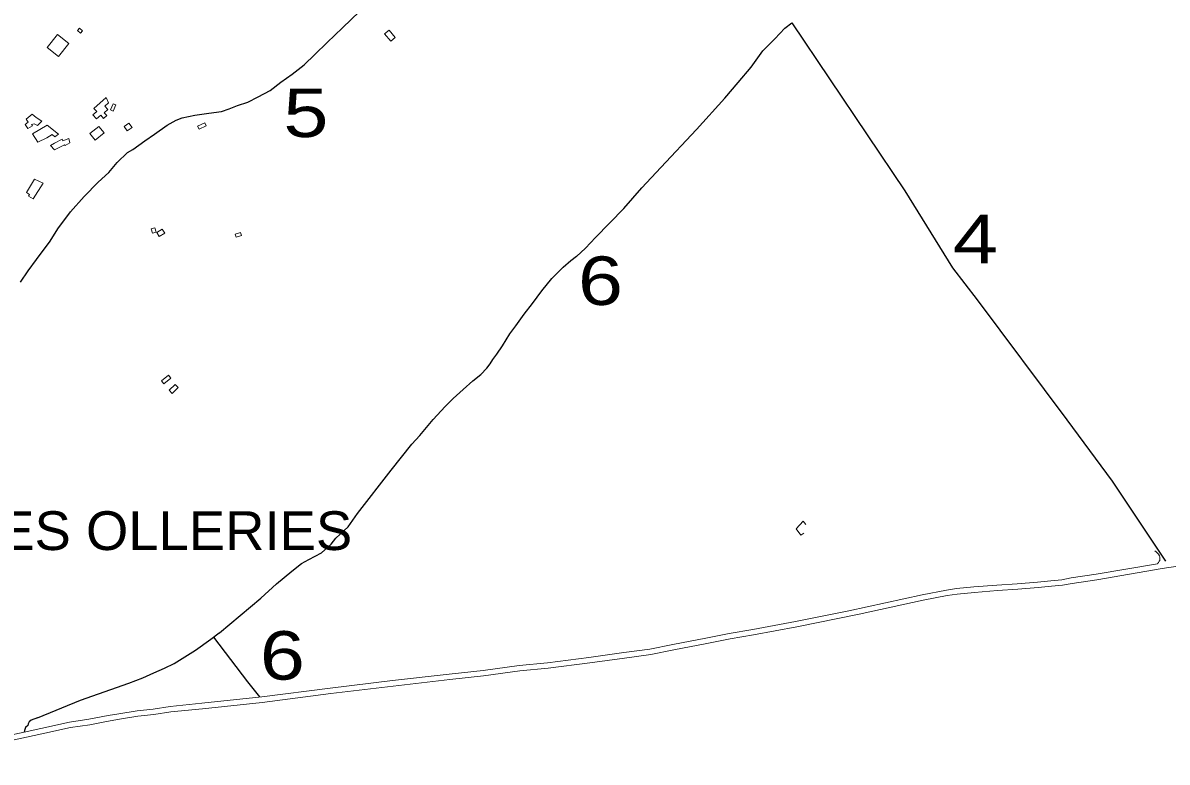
# Model space of a CAD drawing. Extents: x 476989 to 498418, y 4381813 to 4416555.
# Drawn here: x 485600 to 486780, y 4384896 to 4385659 of the extents above; entities that cross this region are included whole.
import ezdxf
from ezdxf.enums import TextEntityAlignment as Align

# ---------------------------------------------------------------- set-up
doc = ezdxf.new("R2010")
doc.units = 0
doc.header["$LTSCALE"] = 20
doc.linetypes.add('MEDIUM_DASHED', pattern=[4.5, 3, -1.5])
for name, color, linetype, lineweight in [('13', 7, 'Continuous', 13), ('36', 7, 'Continuous', 13), ('47', 7, 'Continuous', 13), ('48', 7, 'MEDIUM_DASHED', 13), ('6', 7, 'Continuous', 25)]:
    doc.layers.add(name, color=color, linetype=linetype, lineweight=lineweight)
doc.layers.add('7', color=7, linetype='Continuous')

msp = doc.modelspace()

# ---------------------------------------------------------------- linework, layer by layer
at = {"layer": '36'}
for points in [[(485587.94, 4384918.87), (485619.65, 4384925.47), (485648.99, 4384932.03), (485669.04, 4384935.03), (485686.15, 4384938.36), (485699.65, 4384940.84), (485718.69, 4384943.79), (485734.94, 4384945.58), (485752.53, 4384948.26), (485785.29, 4384951.54), (485846.98, 4384958.08), (485917.59, 4384967.28), (485981.92, 4384974.91), (486040.54, 4384981.65), (486075.35, 4384985.5), (486112.55, 4384990.45), (486141.85, 4384993.18), (486184.72, 4384998.94), (486220.81, 4385003.83), (486247.67, 4385007.48), (486271.61, 4385012.25), (486305.54, 4385018.75), (486329.76, 4385023.58), (486353.89, 4385027.57), (486398.31, 4385035.88), (486461.13, 4385048.69), (486462.73, 4385049.14), (486528.81, 4385063.65), (486553.7, 4385068.46), (486563.83, 4385069.82), (486581.63, 4385071.52), (486605.36, 4385073.58), (486626.31, 4385074.93), (486647.28, 4385076.51), (486661.18, 4385077.81), (486672.55, 4385078.92), (486682.57, 4385080.87), (486708.05, 4385084.63), (486775.37, 4385096.2), (486800.8, 4385100.04)], [(485601.44, 4384927.38), (485618.46, 4384930.95), (485647.97, 4384937.54), (485668, 4384940.55), (485688.12, 4384944.59), (485698.86, 4384946.38), (485717.96, 4384949.34), (485734.21, 4384951.14), (485751.82, 4384953.82), (485784.71, 4384957.11), (485846.33, 4384963.64), (485916.89, 4384972.84), (485981.27, 4384980.47), (486039.91, 4384987.22), (486074.67, 4384991.06), (486111.92, 4384996.02), (486141.22, 4384998.75), (486183.97, 4385004.49), (486220.05, 4385009.38), (486246.73, 4385013.02), (486270.53, 4385017.75), (486304.46, 4385024.25), (486328.75, 4385029.09), (486352.92, 4385033.1), (486397.22, 4385041.38), (486452.17, 4385052.61), (486452.19, 4385052.58), (486527.68, 4385069.14), (486552.8, 4385074), (486563.2, 4385075.39), (486581.12, 4385077.1), (486604.95, 4385079.16), (486625.92, 4385080.52), (486646.81, 4385082.09), (486660.65, 4385083.38), (486671.74, 4385084.47), (486681.62, 4385086.4), (486707.17, 4385090.17), (486770.61, 4385101.07)], [(485422.69, 4384896.4), (485445.04, 4384898.28), (485457.06, 4384899.22), (485464.89, 4384900.34), (485474.69, 4384902.21), (485508.34, 4384907.79), (485538.44, 4384915.04), (485558.81, 4384919.82), (485586.93, 4384924.38), (485601.44, 4384927.38)]]:
    msp.add_lwpolyline(points, dxfattribs=at)
msp.add_spline([(486767.68, 4385114.39), (486772.5, 4385109.36), (486772.99, 4385106.58), (486772.97, 4385105.38), (486772.81, 4385104.41), (486772.42, 4385103.66), (486770.74, 4385101.28), (486770.61, 4385101.07)], degree=3, dxfattribs=at)
at = {"layer": '47'}
for points in [[(485658.29, 4385653.66), (485661.38, 4385650.92), (485659.34, 4385648.62), (485656.25, 4385651.36)], [(485635.68, 4385647.23), (485647.33, 4385637.86), (485636.56, 4385624.48), (485624.91, 4385633.85)], [(485973.2, 4385647.8), (485979.51, 4385640.27), (485984.18, 4385644.19), (485977.87, 4385651.72)], [(485686, 4385582.05), (485673.31, 4385570.9), (485676.11, 4385567.69), (485672.26, 4385564.34), (485675.87, 4385560.17), (485680.34, 4385564.05), (485683.31, 4385560.61), (485686.6, 4385563.46), (485683.93, 4385566.52), (485687.71, 4385569.83), (485684.68, 4385573.28), (485688.41, 4385576.56)], [(485693.04, 4385575.65), (485690.28, 4385569.34), (485693, 4385568.15), (485695.76, 4385574.46)], [(485619.69, 4385557.64), (485613.67, 4385561.55), (485609.59, 4385565.06), (485603.44, 4385559.82), (485605.27, 4385556.65), (485602.46, 4385554.21), (485604.95, 4385550.05), (485609.94, 4385552.83), (485608.92, 4385554.42), (485611.48, 4385555.06), (485615.13, 4385553.2)], [(485625.19, 4385553.51), (485610.05, 4385544.72), (485615.41, 4385536.24), (485624.62, 4385540.46), (485630.23, 4385543.98), (485632.89, 4385541.54), (485636.84, 4385544.49)], [(485683.68, 4385545.62), (485674.4, 4385538.3), (485669.11, 4385545), (485678.39, 4385552.32)], [(485709.41, 4385555.83), (485704.45, 4385552.39), (485707.72, 4385547.67), (485712.68, 4385551.11)], [(485787.53, 4385556.14), (485780.27, 4385552.57), (485781.8, 4385549.46), (485789.06, 4385553.03)], [(485647.5, 4385539.76), (485641.24, 4385537.45), (485640.36, 4385539.11), (485632.5, 4385534.95), (485628.57, 4385532.83), (485632.55, 4385528.34), (485642.83, 4385533.52), (485643.57, 4385532.76), (485648.26, 4385535.32)], [(485620.73, 4385493.69), (485610.59, 4385477.56), (485605.81, 4385480.55), (485606.79, 4385482.13), (485603.55, 4385484.13), (485612.08, 4385497.96)], [(485736, 4385447.7), (485737.37, 4385443.37), (485733.82, 4385442.25), (485732.45, 4385446.58)], [(485743.71, 4385446.46), (485738.03, 4385443.02), (485740.6, 4385438.78), (485746.28, 4385442.22)], [(485819.05, 4385441.33), (485824.55, 4385443.01), (485825.55, 4385439.73), (485820.05, 4385438.05)], [(485750.18, 4385295.54), (485742.99, 4385289.76), (485745.4, 4385286.76), (485752.59, 4385292.54)], [(485756.95, 4385286.22), (485750.76, 4385280.13), (485753.96, 4385276.88), (485760.15, 4385282.97)]]:
    msp.add_lwpolyline(points, close=True, dxfattribs=at)
at = {"layer": '48'}
msp.add_lwpolyline([(486407.83, 4385141.71), (486405.11, 4385144.87), (486397.87, 4385137.02), (486402.73, 4385130.49), (486405.67, 4385132.69)], dxfattribs=at)
at = {"layer": '6'}
for points in [[(485597.52, 4385391.7), (485605.43, 4385403.19), (485614.06, 4385415.16), (485627.96, 4385433.84), (485636.16, 4385446.72), (485649.17, 4385464.38), (485663.28, 4385479.94), (485677.54, 4385494.69), (485688.56, 4385504.94), (485697.1, 4385515.25), (485707.8, 4385525.57), (485713.5, 4385528.66), (485725.91, 4385537.47), (485735.62, 4385544.46), (485748.75, 4385553.59), (485758, 4385558.72), (485764.17, 4385561.06), (485777.52, 4385563.88), (485791.81, 4385566), (485804.8, 4385567.91), (485812.68, 4385570.49), (485821.36, 4385573.88), (485831.97, 4385577.48), (485842.83, 4385582.78), (485855.2, 4385589.43), (485865.96, 4385597.89), (485877.72, 4385606.2), (485890.29, 4385615.9), (485901.17, 4385626.54), (485913.87, 4385638.89), (485929.7, 4385654.12), (485947.21, 4385671)], [(486171.07, 4385418.2), (486180.45, 4385426.71), (486190.85, 4385437.61), (486220.01, 4385467.74), (486238.45, 4385489.11), (486258.12, 4385510.06), (486294.91, 4385549.3), (486324.2, 4385581.38), (486338.08, 4385597.54), (486351.44, 4385613.56), (486363.48, 4385630.43), (486375.73, 4385642.67), (486386.01, 4385653.7), (486393.28, 4385659.16)], [(486779.18, 4385103.59), (486724.1, 4385186.32), (486677.34, 4385249.63), (486584.76, 4385373.47), (486559.43, 4385406.45), (486510.37, 4385486.01), (486393.48, 4385659.09)], [(485802.83, 4385029.77), (485845.6, 4385065.72), (485861.7, 4385080.31), (485877.49, 4385093.53), (485887.3, 4385101.32), (485895.1, 4385105.6), (485908.18, 4385112.39), (485917.95, 4385121.44), (485922.84, 4385127.37), (485927.25, 4385131.59), (485935.63, 4385139.13), (485945.14, 4385152.95), (485979.77, 4385197.7), (486001.38, 4385224.55), (486009.54, 4385233.3), (486023.28, 4385249.97), (486035.47, 4385263.38), (486043.92, 4385271.58), (486054.18, 4385280.81), (486064.12, 4385289.68), (486072.49, 4385296.54), (486078.51, 4385302.83), (486081.98, 4385307.3), (486084.66, 4385311.91), (486089.01, 4385317.32), (486094.92, 4385325.79), (486102.37, 4385338.44), (486108.49, 4385346.61), (486117.22, 4385358.79), (486125.69, 4385369.55), (486135.5, 4385382.68), (486145.79, 4385395.36), (486157.22, 4385407.13), (486165.44, 4385414.11), (486171.07, 4385418.54)], [(485614.95, 4384942.15), (485659.47, 4384960.27), (485709.16, 4384977.93), (485723.74, 4384983.21), (485735, 4384988.39), (485746.12, 4384993.48), (485756.04, 4384998.3), (485778.17, 4385011.92), (485794.02, 4385023.23), (485802.57, 4385029.77)], [(485796.79, 4385025.24), (485831.62, 4384979.39), (485843.97, 4384963.6)], [(485614.95, 4384942.15), (485608.66, 4384939.57), (485606.61, 4384938.02), (485605.45, 4384935.86), (485604.91, 4384934.22), (485602.76, 4384932.09), (485601.81, 4384930.01), (485601.44, 4384927.75)]]:
    msp.add_lwpolyline(points, dxfattribs=at)

# ---------------------------------------------------------------- texts
at = {"layer": '13', "width": 1.25}
for s, p in [('5', (485891.96, 4385541.41)), ('4', (486582.62, 4385411.14)), ('6', (486195.92, 4385368.17)), ('6', (485867.71, 4384981.53))]:
    msp.add_text(s, height=50, dxfattribs=at).set_placement(p, align=Align.CENTER)
at = {"layer": '7', "width": 1.05}
msp.add_text('SES OLLERIES', height=40, dxfattribs=at).set_placement((485738.4, 4385115.23), align=Align.CENTER)

doc.saveas('drawing.dxf')
